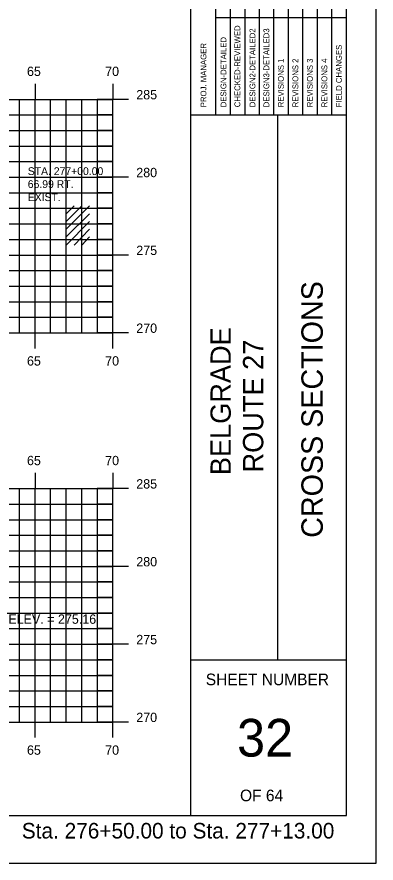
# Model space of a CAD drawing. Extents: x 854008 to 854178, y 366268 to 366378.
# Drawn here: x 854154.9 to 854178, y 366268.2 to 366322.5 of the extents above; entities that cross this region are included whole.
import ezdxf

# ---------------------------------------------------------------- set-up
doc = ezdxf.new("R2010")
doc.units = 0
for name, color, linetype in [('BORDER', 7, 'Continuous'), ('D_Text_Monospaced', 7, 'Continuous'), ('D_Text_Standard', 7, 'Continuous'), ('H_V ANNOTATION', 7, 'Continuous'), ('HIGHWAY_TITLE', 7, 'Continuous'), ('MAJOR', 7, 'Continuous'), ('MINOR', 7, 'Continuous'), ('PLOT BOUNDARY', 7, 'Continuous'), ('S_Buildings', 7, 'Continuous')]:
    doc.layers.add(name, color=color, linetype=linetype)

msp = doc.modelspace()

# ---------------------------------------------------------------- linework, layer by layer
at = {"layer": 'BORDER'}
for p, q in [((854166.103, 366271.236), (854166.103, 366376.239)), ((854176.103, 366271.236), (854176.103, 366376.236)), ((854166.103, 366316.239), (854176.103, 366316.239)), ((854171.694, 366281.239), (854171.694, 366316.239)), ((854166.103, 366281.239), (854176.103, 366281.239)), ((854016.103, 366271.236), (854176.103, 366271.236))]:
    msp.add_line(p, q, dxfattribs=at)
for points in [[(854168.651, 366316.242), (854168.651, 366333.739)], [(854169.582, 366333.739), (854169.582, 366316.242)], [(854170.514, 366316.242), (854170.514, 366333.739)], [(854171.446, 366316.242), (854171.446, 366333.739)], [(854172.377, 366316.242), (854172.377, 366333.739)], [(854173.309, 366316.242), (854173.309, 366333.739)], [(854174.241, 366316.242), (854174.241, 366333.739)], [(854175.172, 366316.242), (854175.172, 366333.739)], [(854167.719, 366316.242), (854167.719, 366333.033)], [(854167.718, 366322.489), (854176.103, 366322.489)]]:
    msp.add_lwpolyline(points, dxfattribs=at)
at = {"layer": 'MAJOR'}
for p, q in [((854156.103, 366318.238), (854156.103, 366317.236)), ((854161.103, 366318.238), (854161.103, 366317.236)), ((854021.103, 366317.236), (854161.103, 366317.236)), ((854021.103, 366317.236), (854161.103, 366317.236)), ((854156.103, 366302.236), (854156.103, 366317.236)), ((854162.105, 366317.236), (854160.101, 366317.236)), ((854161.103, 366302.236), (854161.103, 366317.236)), ((854161.103, 366302.236), (854161.103, 366317.236)), ((854021.103, 366312.236), (854161.103, 366312.236)), ((854162.105, 366312.236), (854160.101, 366312.236)), ((854021.103, 366307.236), (854161.103, 366307.236)), ((854162.105, 366307.236), (854160.101, 366307.236)), ((854021.103, 366302.236), (854161.103, 366302.236)), ((854021.103, 366302.236), (854161.103, 366302.236)), ((854156.103, 366301.234), (854156.103, 366302.236)), ((854162.105, 366302.236), (854160.101, 366302.236)), ((854161.103, 366301.234), (854161.103, 366302.236)), ((854156.103, 366293.238), (854156.103, 366292.236)), ((854161.103, 366293.238), (854161.103, 366292.236)), ((854021.103, 366292.236), (854161.103, 366292.236)), ((854021.103, 366292.236), (854161.103, 366292.236)), ((854156.103, 366277.236), (854156.103, 366292.236)), ((854162.105, 366292.236), (854160.101, 366292.236)), ((854161.103, 366277.236), (854161.103, 366292.236)), ((854161.103, 366277.236), (854161.103, 366292.236)), ((854021.103, 366287.236), (854161.103, 366287.236)), ((854162.105, 366287.236), (854160.101, 366287.236)), ((854021.103, 366282.236), (854161.103, 366282.236)), ((854162.105, 366282.236), (854160.101, 366282.236)), ((854021.103, 366277.236), (854161.103, 366277.236)), ((854021.103, 366277.236), (854161.103, 366277.236)), ((854156.103, 366276.234), (854156.103, 366277.236)), ((854162.105, 366277.236), (854160.101, 366277.236)), ((854161.103, 366276.234), (854161.103, 366277.236))]:
    msp.add_line(p, q, dxfattribs=at)
at = {"layer": 'MINOR'}
for p, q in [((854155.103, 366302.236), (854155.103, 366317.236)), ((854157.103, 366302.236), (854157.103, 366317.236)), ((854158.103, 366302.236), (854158.103, 366317.236)), ((854159.103, 366302.236), (854159.103, 366317.236)), ((854160.103, 366302.236), (854160.103, 366317.236)), ((854021.103, 366316.236), (854161.103, 366316.236)), ((854161.103, 366316.236), (854160.101, 366316.236)), ((854021.103, 366315.236), (854161.103, 366315.236)), ((854161.103, 366315.236), (854160.101, 366315.236)), ((854021.103, 366314.236), (854161.103, 366314.236)), ((854161.103, 366314.236), (854160.101, 366314.236)), ((854021.103, 366313.236), (854161.103, 366313.236)), ((854161.103, 366313.236), (854160.101, 366313.236)), ((854021.103, 366311.236), (854161.103, 366311.236)), ((854161.103, 366311.236), (854160.101, 366311.236)), ((854021.103, 366310.236), (854161.103, 366310.236)), ((854161.103, 366310.236), (854160.101, 366310.236)), ((854021.103, 366309.236), (854161.103, 366309.236)), ((854161.103, 366309.236), (854160.101, 366309.236)), ((854021.103, 366308.236), (854161.103, 366308.236)), ((854161.103, 366308.236), (854160.101, 366308.236)), ((854021.103, 366306.236), (854161.103, 366306.236)), ((854161.103, 366306.236), (854160.101, 366306.236)), ((854021.103, 366305.236), (854161.103, 366305.236)), ((854161.103, 366305.236), (854160.101, 366305.236)), ((854021.103, 366304.236), (854161.103, 366304.236)), ((854161.103, 366304.236), (854160.101, 366304.236)), ((854021.103, 366303.236), (854161.103, 366303.236)), ((854161.103, 366303.236), (854160.101, 366303.236)), ((854155.103, 366277.236), (854155.103, 366292.236)), ((854157.103, 366277.236), (854157.103, 366292.236)), ((854158.103, 366277.236), (854158.103, 366292.236)), ((854159.103, 366277.236), (854159.103, 366292.236)), ((854160.103, 366277.236), (854160.103, 366292.236)), ((854021.103, 366291.236), (854161.103, 366291.236)), ((854161.103, 366291.236), (854160.101, 366291.236)), ((854021.103, 366290.236), (854161.103, 366290.236)), ((854161.103, 366290.236), (854160.101, 366290.236)), ((854021.103, 366289.236), (854161.103, 366289.236)), ((854161.103, 366289.236), (854160.101, 366289.236)), ((854021.103, 366288.236), (854161.103, 366288.236)), ((854161.103, 366288.236), (854160.101, 366288.236)), ((854021.103, 366286.236), (854161.103, 366286.236)), ((854161.103, 366286.236), (854160.101, 366286.236)), ((854021.103, 366285.236), (854161.103, 366285.236)), ((854161.103, 366285.236), (854160.101, 366285.236)), ((854021.103, 366284.236), (854161.103, 366284.236)), ((854161.103, 366284.236), (854160.101, 366284.236)), ((854021.103, 366283.236), (854161.103, 366283.236)), ((854161.103, 366283.236), (854160.101, 366283.236)), ((854021.103, 366281.236), (854161.103, 366281.236)), ((854161.103, 366281.236), (854160.101, 366281.236)), ((854021.103, 366280.236), (854161.103, 366280.236)), ((854161.103, 366280.236), (854160.101, 366280.236)), ((854021.103, 366279.236), (854161.103, 366279.236)), ((854161.103, 366279.236), (854160.101, 366279.236)), ((854021.103, 366278.236), (854161.103, 366278.236)), ((854161.103, 366278.236), (854160.101, 366278.236))]:
    msp.add_line(p, q, dxfattribs=at)
at = {"layer": 'PLOT BOUNDARY'}
msp.add_lwpolyline([(854008.01, 366268.177), (854178.01, 366268.177), (854178.01, 366378.177), (854008.01, 366378.177)], close=True, dxfattribs=at)
at = {"layer": 'S_Buildings'}
for p, q in [((854158.09, 366307.876), (854158.09, 366310.402)), ((854158.09, 366308.893), (854159.599, 366310.402)), ((854158.09, 366309.385), (854159.107, 366310.402)), ((854158.09, 366309.877), (854158.615, 366310.402)), ((854158.09, 366308.401), (854159.599, 366309.877)), ((854158.09, 366307.876), (854159.599, 366309.385)), ((854158.615, 366307.876), (854159.599, 366308.893)), ((854159.107, 366307.876), (854159.599, 366308.401))]:
    msp.add_line(p, q, dxfattribs=at)

# ---------------------------------------------------------------- texts
at = {"layer": 'BORDER'}
for s, height, rotation, p in [('CHECKED-REVIEWED', 0.37275, 90, (854169.284, 366316.727)), ('DESIGN2-DETAILED2', 0.37275, 90, (854170.253, 366316.727)), ('DESIGN3-DETAILED3', 0.37275, 90, (854171.148, 366316.727)), ('DESIGN-DETAILED', 0.37275, 90, (854168.39, 366316.727)), ('PROJ. MANAGER', 0.37275, 90, (854167.108, 366316.727)), ('FIELD CHANGES', 0.37275, 90, (854175.806, 366316.727)), ('REVISIONS 1', 0.37275, 90, (854172.079, 366316.727)), ('REVISIONS 2', 0.37275, 90, (854173.011, 366316.727)), ('REVISIONS 3', 0.37275, 90, (854173.943, 366316.727)), ('REVISIONS 4', 0.37275, 90, (854174.874, 366316.727)), ('CROSS SECTIONS', 1.37787, 90, (854174.588, 366289.073)), ('SHEET NUMBER', 0.74527, 360, (854167.069, 366279.603)), ('32', 2.4194, 360, (854169.079, 366275.019)), ('OF 64', 0.7453, 360, (854169.27, 366272.149))]:
    msp.add_text(s, height=height, rotation=rotation, dxfattribs=at).set_placement(p)
at = {"layer": 'D_Text_Monospaced'}
for s, height, p in [('STA. 277+00.00', 0.49998, (854155.633, 366312.374)), ('66.99 RT.', 0.5, (854155.633, 366311.54)), ('EXIST. ', 0.5, (854155.633, 366310.7))]:
    msp.add_text(s, height=height, dxfattribs=at).set_placement(p)
at = {"layer": 'D_Text_Standard'}
msp.add_text('ELEV. = 275.16', height=0.6, dxfattribs=at).set_placement((854154.383, 366283.548))
at = {"layer": 'H_V ANNOTATION'}
for s, height, p in [('65', 0.6, (854155.581, 366318.736)), ('70', 0.6, (854160.605, 366318.736)), ('285', 0.6, (854162.603, 366317.236)), ('280', 0.6, (854162.603, 366312.236)), ('275', 0.6, (854162.603, 366307.236)), ('270', 0.6, (854162.603, 366302.236)), ('65', 0.6, (854155.581, 366300.136)), ('70', 0.6, (854160.605, 366300.136)), ('65', 0.6, (854155.581, 366293.736)), ('70', 0.6, (854160.605, 366293.736)), ('285', 0.6, (854162.603, 366292.236)), ('280', 0.6, (854162.603, 366287.236)), ('275', 0.6, (854162.603, 366282.236)), ('270', 0.6, (854162.603, 366277.236)), ('65', 0.6, (854155.581, 366275.136)), ('70', 0.6, (854160.605, 366275.136)), ('Sta. 276+50.00 to Sta. 277+13.00', 1.0002, (854155.249, 366269.756))]:
    msp.add_text(s, height=height, dxfattribs=at).set_placement(p)
at = {"layer": 'HIGHWAY_TITLE'}
for s, p in [('BELGRADE', (854168.676, 366293.095)), ('ROUTE 27', (854170.763, 366293.269))]:
    msp.add_text(s, height=1.3043, rotation=90, dxfattribs=at).set_placement(p)

doc.saveas('drawing.dxf')
